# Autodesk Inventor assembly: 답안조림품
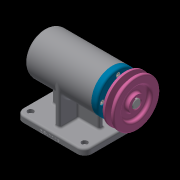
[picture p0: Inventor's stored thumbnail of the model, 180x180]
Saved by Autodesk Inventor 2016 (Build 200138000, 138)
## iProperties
Created: 2020-10
Part Number: 답안조림품
Material: 일반
Document SubType Name: Assembly
Designer: 605-04
Author: 605-04
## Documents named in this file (11)
- C:\Users\605-04\Desktop\701004V1006\답안조림품.iam
- C:\Users\605-04\Documents\Inventor\프로젝트 이름\701004V1006\본체.ipt
- C:\Users\605-04\Desktop\701004V1006\축.ipt
- C:\Users\605-04\Desktop\701004V1006\베어링 6004.ipt
- C:\Users\605-04\Desktop\701004V1006\어댑터슬리브.ipt
- C:\Users\605-04\Desktop\701004V1006\볼트 M4.ipt
- C:\Users\605-04\Desktop\701004V1006\베어링 51202.ipt
- C:\Users\605-04\Desktop\701004V1006\커버.ipt
- C:\Users\605-04\Desktop\701004V1006\키 5 x 5 x 16.ipt
- C:\Users\605-04\Desktop\701004V1006\V벨트풀리.ipt
- C:\Users\605-04\Desktop\701004V1006\멈춤나사 M3.ipt
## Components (1 placed, 1 different names)
1. V벨트풀리:1 — 플러쉬:2
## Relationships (1: Flush 1)
- 플러쉬:2 [Flush]: V벨트풀리:1
